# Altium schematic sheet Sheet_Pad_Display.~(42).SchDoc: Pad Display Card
size A4; Date: 08/05/2013; ApprovedBy: Vincenzo Niespolo; CheckedBy: Vincenzo Niespolo; Author: Vincenzo Niespolo; CompanyName: NiespoTech; DrawnBy: Vincenzo Niespolo; Engineer: Vincenzo Niespolo; Organization: NiespoTech; Address1: Viale E. De Amicis n°39; Address2: Imola (BO); Address3: Cell. +39 334 9113322; Address4: e-mail: niespotech@gmail.com; DocumentNumber: 1; Revision: 00; SheetNumber: 1; SheetTotal: 5
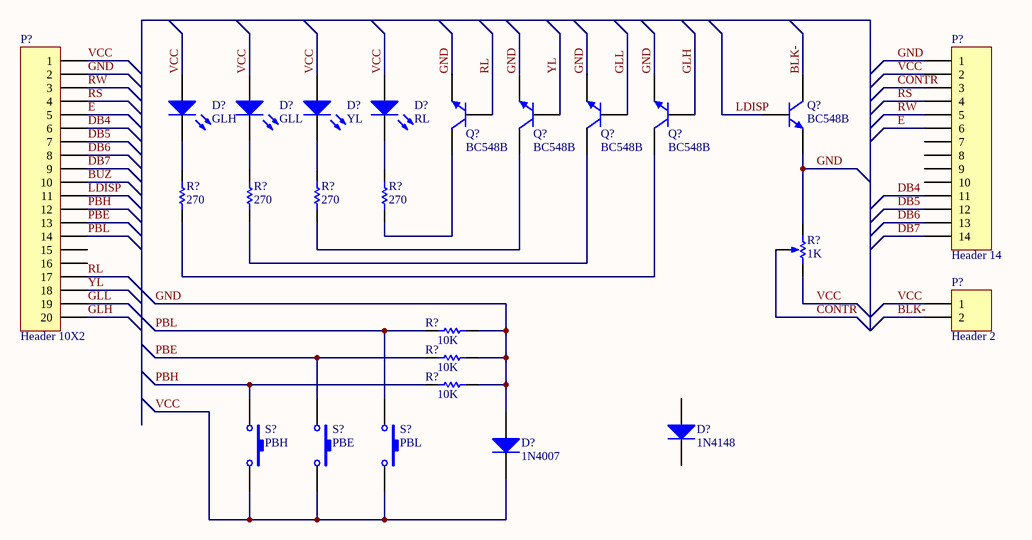
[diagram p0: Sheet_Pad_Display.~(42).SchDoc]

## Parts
(Parts that share a designator on the sheet are numbered #1, #2 ... from top to bottom, then left to right.)
D?#1  GLH  [LED-1]
D?#2  GLL  [LED-1]
D?#3  YL  [LED-1]
D?#4  RL  [LED-1]
D?#5  1N4148  [DO-35]
D?#6  1N4007  [DO-41]
P?#1  Header 10X2  [HDR2X10_CEN]
P?#2  Header 14  [HDR1X14]
P?#3  Header 2  [HDR1X2]
Q?#1  BC548B  [29-04]
Q?#2  BC548B  [29-04]
Q?#3  BC548B  [29-04]
Q?#4  BC548B  [29-04]
Q?#5  BC548B  [29-04]
R?#1  270  [AXIAL-0.3]
R?#2  270  [AXIAL-0.3]
R?#3  270  [AXIAL-0.3]
R?#4  270  [AXIAL-0.3]
R?#5  1K  [VR5]
R?#6  10K  [AXIAL-0.3]
R?#7  10K  [AXIAL-0.3]
R?#8  10K  [AXIAL-0.3]
S?#1  PBH  [SPST-2]
S?#2  PBE  [SPST-2]
S?#3  PBL  [SPST-2]

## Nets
BLK-: P?#3.2 Q?#1.1(C)
BUZ: P?#1.10
CONTR: P?#2.3 R?#5.3(TAP)
DB4: P?#1.6 P?#2.11
DB5: P?#1.7 P?#2.12
DB6: P?#1.8 P?#2.13
DB7: P?#1.9 P?#2.14
E: P?#1.5 P?#2.6
GLH: P?#1.20 Q?#5.2(B)
GLL: P?#1.19 Q?#4.2(B)
GND: D?#6.1(A) P?#1.2 P?#2.1 Q?#1.3(E) Q?#2.3(E) Q?#3.3(E) Q?#4.3(E) Q?#5.3(E) R?#5.1(TOP) R?#6.1 R?#7.1 R?#8.1
LDISP: P?#1.11 Q?#1.2(B)
PBE: P?#1.13 R?#7.2 S?#2.1
PBH: P?#1.12 R?#8.2 S?#1.1
PBL: P?#1.14 R?#6.2 S?#3.1
RL: P?#1.17 Q?#2.2(B)
RS: P?#1.4 P?#2.4
RW: P?#1.3 P?#2.5
VCC: D?#1.1(A) D?#2.1(A) D?#3.1(A) D?#4.1(A) D?#6.2(K) P?#1.1 P?#2.2 P?#3.1 R?#5.2(BOT) S?#1.2 S?#2.2 S?#3.2
YL: P?#1.18 Q?#3.2(B)
NetD?#1_2: D?#1.2(K) R?#1.2
NetD?#2_2: D?#2.2(K) R?#2.2
NetD?#3_2: D?#3.2(K) R?#3.2
NetD?#4_2: D?#4.2(K) R?#4.2
NetQ?#2_1: Q?#2.1(C) R?#4.1
NetQ?#3_1: Q?#3.1(C) R?#3.1
NetQ?#4_1: Q?#4.1(C) R?#2.1
NetQ?#5_1: Q?#5.1(C) R?#1.1

Not connected (* = marked no-connect by the designer): D?#5 1(A) 2(K); P?#1 15 16; P?#2 7 8 9 10

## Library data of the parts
D?#1-D?#4 = LED1: Typical RED GaAs LED
D?#5 = Diode 1N4148: High Conductance Fast Diode
D?#6 = Diode 1N4007: 1 Amp General Purpose Rectifier
P?#1 = Header 20: Header, 20-Pin
P?#2 = Header 14: Header, 14-Pin
P?#3 = Header 2: Header, 2-Pin
Q?#1-Q?#5 = BC548B: Amplifier Transistor NPN Silicon
R?#1-R?#4 R?#6-R?#8 = Res1: Resistor
R?#5 = RPot: Potentiometer; Sim Note: Enter the Resistance value and the set point into parameter fields.; Set Position: 0.5
S?#1-S?#3 = SW-PB: Switch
